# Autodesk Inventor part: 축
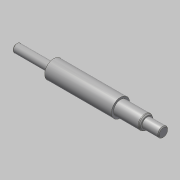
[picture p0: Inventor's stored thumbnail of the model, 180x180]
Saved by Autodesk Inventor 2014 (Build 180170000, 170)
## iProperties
Created: 2016-05
Part Number: 축
Document SubType Name: Modeling
Designer: mduedu
Density: 7.86 g/cm^3
Material: 강철, 연강
Appearance: Steel
Author: mduedu
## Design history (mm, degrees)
sketch "스케치1"
  geometry: L1 (-44, 11)-(-44, 5); L2 (37, 11)-(37, 8.5); L3 (-89, 0)-(89, 0); L4 (-44, 11)-(37, 11); L5 (37, 11)-(37, 8.5); L6 (-44, 11)-(-44, 5); L7 (-44, 5)-(-89, 5); L8 (-89, 5)-(-89, 0); L9 (37, 8.5)-(69, 8.5); L10 (89, 6)-(89, 0); L11 (69, 8.5)-(69, 6); L12 (69, 6)-(89, 6); 1 further point
  constraints: 24 end point, 9 perpendicular, 2 midpoint, 1 horizontal
  dimensions: "d0" = 22 diameter of L4 L3; "d1" = 10 diameter of L7 L3; "d2" = 45 distance between parallel lines of L8 L1; "d3" = 52 distance between parallel lines of L10 L2; "d4" = 12 diameter of L12 L3; "d5" = 20 distance between parallel lines of L10 L11; "d29" = 81 distance of L1.start L2.start; "d37" = 17 diameter of L9 L3
revolve "회전1" stored, may be unused: angle "d6" = 90 deg
chamfer "모따기2" distance "d32" = 1; stored, may be unused: second distance "d33" = 2, angle "d34" = 45 deg
node "작업 평면4"
sketch "스케치4"
  geometry: L1 (-5, 2)-(5, 2); L2 (5, -2)-(-5, -2); L3 (-10, -5)-(-10, 5) reference; A1 r 2 centre (5, 0) between (5, -2) and (5, 2); A2 r 2 centre (-5, 0) between (-5, 2) and (-5, -2); 1 further point
  constraints: 4 end point, 4 point on circle, 4 tangent, 2 centre point, 1 horizontal, 1 horizontal alignment, 1 parallel
  dimensions: "d20" = 4 distance between parallel lines of L2 L1; "d21" = 14 dimension on A1 A2; "d35" = 3 distance edge to line of A2 L3
extrude "돌출3" cut sketch "스케치4" distance "d23" = 2.5; taper "d24" = 0 deg
node "작업 평면5"
sketch "스케치5"
  geometry: L1 (22.5, 1.5)-(12, 1.5); L2 (12, -1.5)-(22.5, -1.5); L3 (22.5, 4)-(22.5, -4) reference; A1 r 1.5 centre (12, 0) between (12, 1.5) and (12, -1.5); 3 further points
  constraints: 4 end point, 2 horizontal alignment, 2 point on circle, 2 point on line, 2 tangent, 1 centre point, 1 coincident, 1 horizontal, 1 midpoint
  dimensions: "d25" = 3 distance between parallel lines of L2 L1; "d36" = 12 dimension on A1 L3
extrude "돌출4" cut sketch "스케치5" distance "d27" = 1.8; taper "d28" = 0 deg
chamfer "모따기3" distance "d38" = 1.82; stored, may be unused: second distance "d39" = 2, angle "d40" = 30 deg
fillet "모깎기1" dims "d41" = 2
node "솔리드1"
